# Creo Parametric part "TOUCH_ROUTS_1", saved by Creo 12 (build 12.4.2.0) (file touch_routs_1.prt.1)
Units: Custom; MM, KILOGRAM, SECS

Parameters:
  PTC_WM_ITERATION = "0"
  PTC_WM_VERSION = "-.0"
  PTC_WM_LIFECYCLE_STATE = "In Work"
  PTC_WM_LIFECYCLE = "MO_CADDocument"
  PTC_WM_CREATED_BY = "Maximilian Roepper (Z0017RMS: MO)"
  PTC_WM_CREATED_ON = "18-Sep-26 11:36:42 AM"
  PTC_WM_MODIFIED_BY = "Maximilian Roepper (Z0017RMS: MO)"
  PTC_WM_MODIFIED_ON = "18-Sep-26 11:36:46 AM"
  PDMLINKNUMBER = "PDM000071454881"
  PTC_WM_NAME = "touch_routs_1.prt"
  PTC_WM_NUMBER = "PDM000071454881"

Other parameters: WEIGHT, WEIGHT_FACTOR, WEIGHT_ADD, _MASS_TEMP, _DIFF_TEMP, MC_ERRORS, SUPPLIER

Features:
  1. coordinate system
  2. datum plane "PRT_YZ"
  3. datum plane "PRT_XY"
  4. datum plane "PRT_XZ"
  5. coordinate system
  6. datum axis
  7. datum axis
  8. datum axis
  9. coordinate system
  10. imported feature

Other named items: PRT, SIEMENS_MO, DRW_VIEW_ORG, PRT_X, PRT_Y, PRT_Z, CS0, ROUGH_GROB

Layers: 00_STD_CSYS-KSYS, 01_STD_PLANES-EBENEN, 02_STD_AXES-ACHSEN, 03_STD_CSYS-KSYS, 24_IMPORT_FEAT-IMPORT_KE

Surfaces: 44 plane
